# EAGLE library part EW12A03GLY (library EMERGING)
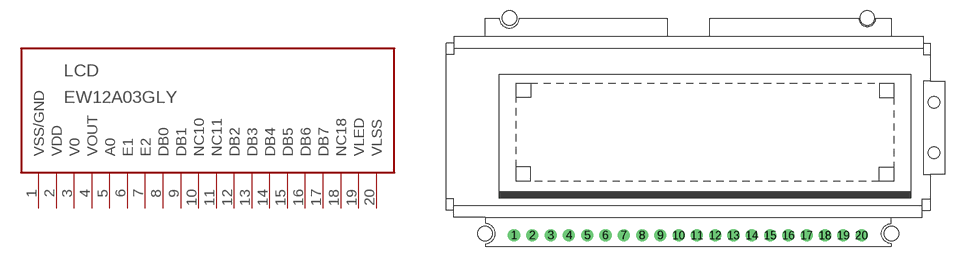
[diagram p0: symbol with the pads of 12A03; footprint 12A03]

Designator prefix LCD

## EW12A03GLY  [12A03]
1  VSS/GND  pwr
2  VDD  pwr
3  V0  in
4  VOUT  out
5  A0  in
6  E1  in
7  E2  in
8  DB0  in
9  DB1  in
10  NC10  nc
11  NC11  nc
12  DB2  in
13  DB3  in
14  DB4  in
15  DB5  in
16  DB6  in
17  DB7  in
18  NC18  nc
19  VLED  in
20  VLSS  in

## Footprint 12A03 (pad centres in mm)
drill 1 pad 1.676 round: 1 0,0; 2 2.54,0; 3 5.08,0; 4 7.62,0; 5 10.16,0; 6 12.7,0; 7 15.24,0; 8 17.78,0; 9 20.32,0; 10 22.86,0; 11 25.4,0; 12 27.94,0; 13 30.48,0; 14 33.02,0; 15 35.56,0; 16 38.1,0; 17 40.64,0; 18 43.18,0; 19 45.72,0; 20 48.26,0
hole 2 at -4,0.25
hole 2 at 52.4,0.25
hole 2 at -0.65,30.25
hole 2 at 49.05,30.25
